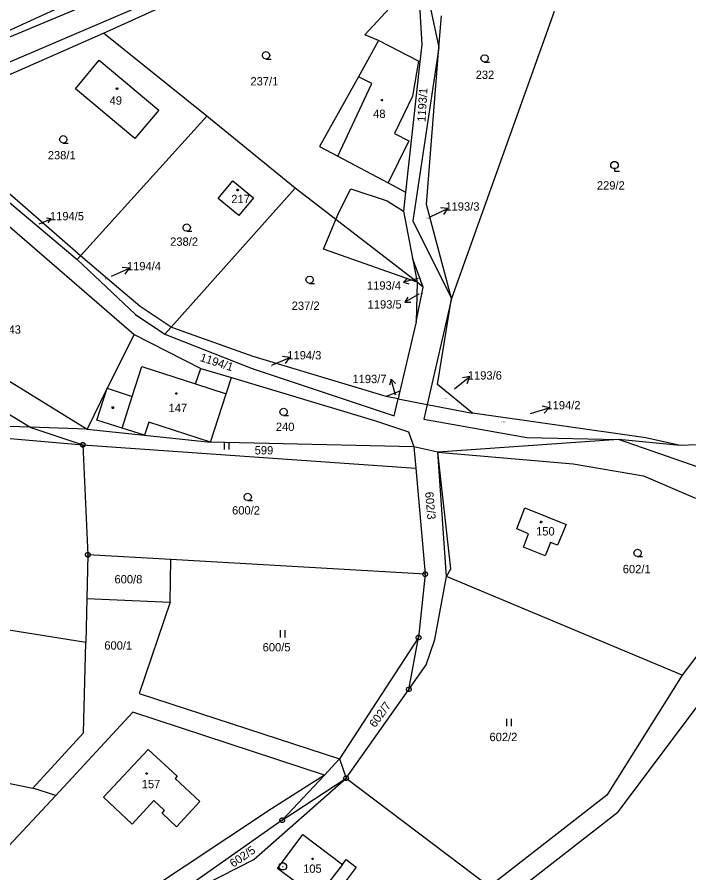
# Model space of a CAD drawing. Extents: x -694465 to -690527, y -983694 to -978978.
# Drawn here: x -692275 to -692137.7, y -981883.1 to -981708.4 of the extents above; entities that cross this region are included whole.
import ezdxf

# ---------------------------------------------------------------- set-up
doc = ezdxf.new("R2010")
doc.units = 0
for name, color, linetype in [('Vrstva 1', 7, 'Continuous'), ('Vrstva 16', 7, 'Continuous'), ('Vrstva 18', 7, 'Continuous'), ('Vrstva 19', 7, 'Continuous'), ('Vrstva 24', 7, 'Continuous'), ('Vrstva 25', 7, 'Continuous'), ('Vrstva 29', 7, 'Continuous')]:
    doc.layers.add(name, color=color, linetype=linetype)

msp = doc.modelspace()

# ---------------------------------------------------------------- linework, layer by layer
at = {"layer": 'Vrstva 1'}
msp.add_line((-692272.4, -981792.13), (-692261.55, -981795.71), dxfattribs=at)
for points in [[(-692257.29, -981711.65), (-692205.67, -981688.24)], [(-692231.78, -981693.79), (-692280.66, -981714.19)], [(-692192.79, -981696.05), (-692188.8, -981714.62)], [(-692278.89, -981718.56), (-692230.3, -981697.74)], [(-692250.23, -981699), (-692281.2, -981713.23)], [(-692203.9, -981712.02), (-692193.1, -981700.2)], [(-692193.1, -981700.2), (-692192.27, -981713.96)], [(-692188.8, -981714.62), (-692188.29, -981708.14)], [(-692165.23, -981707.27), (-692186.21, -981765.83)], [(-692296.96, -981729.07), (-692257.29, -981711.65)], [(-692236.23, -981728.62), (-692257.29, -981711.65)], [(-692201.12, -981713.15), (-692203.9, -981712.02)], [(-692201.12, -981713.15), (-692205.25, -981720.56)], [(-692192.99, -981717.35), (-692201.12, -981713.15)], [(-692192.27, -981713.96), (-692192.67, -981717.51)], [(-692188.8, -981714.62), (-692194.09, -981749.95)], [(-692191.32, -981746.65), (-692188.8, -981714.62)], [(-692258.2, -981717.18), (-692246.03, -981727.37), (-692250.9, -981733.19), (-692263.07, -981723), (-692258.2, -981717.18)], [(-692192.99, -981717.35), (-692194.2, -981724.54)], [(-692192.67, -981717.51), (-692192.99, -981717.35)], [(-692192.67, -981717.51), (-692195.6, -981744.14)], [(-692205.25, -981720.56), (-692213.2, -981734.83)], [(-692202.48, -981721.94), (-692205.25, -981720.56)], [(-692209.46, -981736.81), (-692202.48, -981721.94)], [(-692194.2, -981724.54), (-692197.87, -981732.16)], [(-692296.96, -981729.07), (-692262.73, -981757.9)], [(-692236.23, -981728.62), (-692262.05, -981757.15)], [(-692218.17, -981743.32), (-692236.23, -981728.62)], [(-692197.87, -981732.16), (-692194.95, -981733.63)], [(-692213.2, -981734.83), (-692209.46, -981736.81)], [(-692194.95, -981733.63), (-692199.19, -981742.24)], [(-692209.46, -981736.81), (-692199.19, -981742.24)], [(-692262.05, -981757.15), (-692280.84, -981740.82)], [(-692233.88, -981745.4), (-692230.87, -981741.79), (-692226.65, -981745.3), (-692229.65, -981748.88), (-692233.88, -981745.4)], [(-692243.51, -981771.7), (-692218.17, -981743.32)], [(-692209.86, -981749.73), (-692218.17, -981743.32)], [(-692209.12, -981748), (-692206.78, -981743.47)], [(-692206.78, -981743.47), (-692199.37, -981745.92)], [(-692199.19, -981742.24), (-692195.6, -981744.14)], [(-692195.6, -981744.14), (-692196.03, -981747.99)], [(-692199.37, -981745.92), (-692196.03, -981747.99)], [(-692186.21, -981765.83), (-692191.32, -981746.65)], [(-692209.86, -981749.73), (-692209.12, -981748)], [(-692196.03, -981747.99), (-692194.19, -981757.63)], [(-692279.142, -981748.931), (-692251.02, -981773.17)], [(-692212.4, -981755.73), (-692209.86, -981749.73)], [(-692193.26, -981762.53), (-692209.86, -981749.73)], [(-692194.09, -981749.95), (-692186.21, -981765.83)], [(-692193.26, -981762.53), (-692212.4, -981755.73)], [(-692262.73, -981757.9), (-692262.05, -981757.15)], [(-692254.63, -981763.4), (-692262.05, -981757.15)], [(-692194.19, -981757.63), (-692193.26, -981762.53)], [(-692192, -981763.5), (-692194.19, -981757.63)], [(-692262.73, -981757.9), (-692250.76, -981769.09)], [(-692193.26, -981762.53), (-692193.44, -981770.63)], [(-692192, -981763.5), (-692193.26, -981762.53)], [(-692249.84, -981767.44), (-692254.63, -981763.4)], [(-692193.44, -981770.63), (-692192, -981763.5)], [(-692186.21, -981765.83), (-692191.17, -981787.48)], [(-692189.06, -981783.4), (-692186.21, -981765.83)], [(-692243.51, -981771.7), (-692249.84, -981767.44)], [(-692250.76, -981769.09), (-692244.76, -981773.11)], [(-692193.44, -981770.63), (-692196.77, -981784.74)], [(-692251.02, -981773.17), (-692256.56, -981784.17)], [(-692251.02, -981773.17), (-692237.44, -981780.11)], [(-692244.76, -981773.11), (-692243.51, -981771.7)], [(-692244.76, -981773.11), (-692226.97, -981780.11)], [(-692240.7, -981772.7), (-692243.51, -981771.7)], [(-692226.77, -981777.67), (-692240.7, -981772.7)], [(-692199.6, -981785.85), (-692226.77, -981777.67)], [(-692251.44, -981785.82), (-692249.49, -981779.75)], [(-692249.49, -981779.75), (-692238.49, -981783.28)], [(-692238.49, -981783.28), (-692237.44, -981780.11)], [(-692237.44, -981780.11), (-692231.2, -981781.97)], [(-692226.97, -981780.11), (-692197.91, -981789.76)], [(-692232.27, -981785.28), (-692231.2, -981781.97)], [(-692231.2, -981781.97), (-692201.94, -981790.73)], [(-692276.89, -981782.51), (-692260.66, -981792.53)], [(-692238.49, -981783.28), (-692232.27, -981785.28)], [(-692181.96, -981789.26), (-692189.06, -981783.4)], [(-692256.56, -981784.17), (-692260.66, -981792.53)], [(-692258.65, -981790.66), (-692256.56, -981784.17)], [(-692256.56, -981784.17), (-692251.44, -981785.82)], [(-692235.44, -981795.15), (-692232.27, -981785.28)], [(-692196.77, -981784.74), (-692199.6, -981785.85)], [(-692196.77, -981784.74), (-692197.13, -981786.33)], [(-692272.4, -981792.13), (-692280.59, -981787.14)], [(-692253.52, -981792.3), (-692251.44, -981785.82)], [(-692197.13, -981786.33), (-692199.6, -981785.85)], [(-692197.91, -981789.76), (-692197.13, -981786.33)], [(-692197.13, -981786.33), (-692191.17, -981787.48)], [(-692191.17, -981787.48), (-692191.86, -981790.49)], [(-692191.17, -981787.48), (-692181.96, -981789.26)], [(-692253.52, -981792.3), (-692258.65, -981790.66)], [(-692201.94, -981790.73), (-692195, -981793.05)], [(-692191.86, -981790.49), (-692170.86, -981794.21)], [(-692146.51, -981794.26), (-692181.96, -981789.26)], [(-692272.4, -981792.13), (-692286.84, -981791.64)], [(-692260.66, -981792.53), (-692272.4, -981792.13)], [(-692260.66, -981792.53), (-692248.95, -981793.77)], [(-692248.95, -981793.77), (-692253.52, -981792.3)], [(-692248.09, -981791.08), (-692248.95, -981793.77)], [(-692235.44, -981795.15), (-692248.09, -981791.08)], [(-692287.43, -981793.47), (-692261.55, -981795.71)], [(-692248.95, -981793.77), (-692235.44, -981795.15)], [(-692195, -981793.05), (-692193.92, -981796.12)], [(-692170.86, -981794.21), (-692152.09, -981794.64)], [(-692139.51, -981795.86), (-692146.51, -981794.26)], [(-692261.55, -981795.71), (-692260.51, -981818.15)], [(-692261.55, -981795.71), (-692193.53, -981800.46)], [(-692193.92, -981796.12), (-692235.44, -981795.15)], [(-692152.09, -981794.64), (-692189.03, -981797.21)], [(-692139.51, -981795.86), (-692152.09, -981794.64)], [(-692119.15, -981806.07), (-692152.09, -981794.64)], [(-692136.04, -981795.7), (-692139.51, -981795.86)], [(-692193.92, -981796.12), (-692193.53, -981800.46)], [(-692189.03, -981797.21), (-692193.92, -981796.12)], [(-692186.33, -981821.04), (-692189.03, -981797.21)], [(-692189.03, -981797.21), (-692161.37, -981799.58)], [(-692187.24, -981822.58), (-692189.03, -981797.21)], [(-692161.37, -981799.58), (-692147.02, -981802.05)], [(-692193.53, -981800.46), (-692191.62, -981822.11)], [(-692147.02, -981802.05), (-692136.35, -981806.57)], [(-692162.81, -981812), (-692164.57, -981816.23), (-692166, -981815.65), (-692167.11, -981818.36), (-692171.53, -981816.58), (-692170.46, -981813.85), (-692172.9, -981812.87), (-692171.23, -981808.59), (-692162.81, -981812)], [(-692260.51, -981818.15), (-692260.72, -981827.06)], [(-692243.54, -981819.13), (-692260.51, -981818.15)], [(-692243.72, -981827.83), (-692243.54, -981819.13)], [(-692191.62, -981822.11), (-692243.54, -981819.13)], [(-692191.62, -981822.11), (-692192.95, -981835.08)], [(-692187.24, -981822.58), (-692186.33, -981821.04)], [(-692189.61, -981835.48), (-692187.24, -981822.58)], [(-692139.1, -981842.77), (-692187.24, -981822.58)], [(-692260.72, -981827.06), (-692260.94, -981836.06)], [(-692260.72, -981827.06), (-692243.72, -981827.83)], [(-692243.72, -981827.83), (-692250.03, -981846.51)], [(-692260.94, -981836.06), (-692300.55, -981829.71)], [(-692128.92, -981829.39), (-692139.1, -981842.77)], [(-692152.17, -981870.62), (-692124.32, -981833.57)], [(-692261.4, -981854.49), (-692260.94, -981836.06)], [(-692192.95, -981835.08), (-692209.09, -981859.82)], [(-692194.95, -981845.63), (-692192.95, -981835.08)], [(-692191.43, -981840.64), (-692189.61, -981835.48)], [(-692194.95, -981845.63), (-692191.43, -981840.64)], [(-692139.1, -981842.77), (-692154.49, -981867.24)], [(-692250.03, -981846.51), (-692209.09, -981859.82)], [(-692207.77, -981863.76), (-692194.95, -981845.63)], [(-692251.3, -981850.3), (-692267.06, -981867.3)], [(-692212.18, -981863.13), (-692251.3, -981850.3)], [(-692271.78, -981865.78), (-692261.4, -981854.49)], [(-692308.11, -981858.37), (-692271.78, -981865.78)], [(-692242.71, -981863.81), (-692237.61, -981868.56), (-692242.41, -981873.67), (-692245.36, -981870.94), (-692244.84, -981870.38), (-692247.02, -981868.36), (-692251.45, -981873.14), (-692257.32, -981867.66), (-692248.18, -981857.88), (-692242.3, -981863.36), (-692242.71, -981863.81)], [(-692209.09, -981859.82), (-692212.18, -981863.13)], [(-692209.09, -981859.82), (-692207.77, -981863.76)], [(-692226.61, -981880.38), (-692207.77, -981863.76)], [(-692212.18, -981863.13), (-692222.98, -981870.05)], [(-692212.18, -981863.13), (-692220.82, -981872.37)], [(-692220.82, -981872.37), (-692207.77, -981863.76)], [(-692207.77, -981863.76), (-692178.46, -981885.9)], [(-692267.06, -981867.3), (-692271.78, -981865.78)], [(-692267.06, -981867.3), (-692298.87, -981901.26)], [(-692154.49, -981867.24), (-692178.46, -981885.9)], [(-692222.98, -981870.05), (-692249.34, -981887.51)], [(-692194.4, -981903.52), (-692152.17, -981870.62)], [(-692220.82, -981872.37), (-692247.01, -981890.78)], [(-692212.93, -981887.14), (-692213.73, -981888.21), (-692221.78, -981882.18), (-692216.62, -981875.29), (-692208.46, -981881.4)], [(-692247.01, -981890.78), (-692226.61, -981880.38)], [(-692208.46, -981881.4), (-692212.93, -981887.14)], [(-692208.46, -981881.4), (-692207.71, -981880.4), (-692205.7, -981881.91)], [(-692205.7, -981881.91), (-692210.81, -981888.73), (-692212.93, -981887.14)]]:
    msp.add_lwpolyline(points, dxfattribs=at)
at = {"layer": 'Vrstva 24'}
for points in [[(-692261.396, -981795.234), (-692261.146, -981795.416), (-692261.05, -981795.71), (-692261.146, -981796.004), (-692261.396, -981796.186), (-692261.704, -981796.186), (-692261.954, -981796.004), (-692262.05, -981795.71), (-692261.954, -981795.416), (-692261.704, -981795.234)], [(-692260.356, -981817.674), (-692260.106, -981817.856), (-692260.01, -981818.15), (-692260.106, -981818.444), (-692260.356, -981818.626), (-692260.664, -981818.626), (-692260.914, -981818.444), (-692261.01, -981818.15), (-692260.914, -981817.856), (-692260.664, -981817.674)], [(-692191.466, -981821.634), (-692191.216, -981821.816), (-692191.12, -981822.11), (-692191.216, -981822.404), (-692191.466, -981822.586), (-692191.774, -981822.586), (-692192.024, -981822.404), (-692192.12, -981822.11), (-692192.024, -981821.816), (-692191.774, -981821.634)], [(-692192.796, -981834.604), (-692192.546, -981834.786), (-692192.45, -981835.08), (-692192.546, -981835.374), (-692192.796, -981835.556), (-692193.104, -981835.556), (-692193.354, -981835.374), (-692193.45, -981835.08), (-692193.354, -981834.786), (-692193.104, -981834.604)], [(-692194.796, -981845.154), (-692194.546, -981845.336), (-692194.45, -981845.63), (-692194.546, -981845.924), (-692194.796, -981846.106), (-692195.104, -981846.106), (-692195.354, -981845.924), (-692195.45, -981845.63), (-692195.354, -981845.336), (-692195.104, -981845.154)], [(-692207.616, -981863.284), (-692207.366, -981863.466), (-692207.27, -981863.76), (-692207.366, -981864.054), (-692207.616, -981864.236), (-692207.924, -981864.236), (-692208.174, -981864.054), (-692208.27, -981863.76), (-692208.174, -981863.466), (-692207.924, -981863.284)], [(-692220.666, -981871.894), (-692220.416, -981872.076), (-692220.32, -981872.37), (-692220.416, -981872.664), (-692220.666, -981872.846), (-692220.974, -981872.846), (-692221.224, -981872.664), (-692221.32, -981872.37), (-692221.224, -981872.076), (-692220.974, -981871.894)], [(-692220.486, -981881.066), (-692220.15, -981881.26), (-692219.956, -981881.596), (-692219.956, -981881.984), (-692220.15, -981882.32), (-692220.486, -981882.514), (-692220.874, -981882.514), (-692221.21, -981882.32), (-692221.404, -981881.984), (-692221.404, -981881.596), (-692221.21, -981881.26), (-692220.874, -981881.066)]]:
    msp.add_lwpolyline(points, close=True, dxfattribs=at)
for points in [[(-692261.669, -981795.71), (-692261.43, -981795.71)], [(-692260.629, -981818.15), (-692260.39, -981818.15)], [(-692191.739, -981822.11), (-692191.5, -981822.11)], [(-692193.069, -981835.08), (-692192.83, -981835.08)], [(-692195.069, -981845.63), (-692194.83, -981845.63)], [(-692207.889, -981863.76), (-692207.65, -981863.76)], [(-692220.939, -981872.37), (-692220.7, -981872.37)], [(-692220.73, -981881.79), (-692220.63, -981881.79)]]:
    msp.add_lwpolyline(points, dxfattribs=at)
at = {"layer": 'Vrstva 25'}
for points in [[(-692224.09, -981716.94), (-692224.465, -981716.839), (-692224.739, -981716.565), (-692224.84, -981716.19), (-692224.739, -981715.815), (-692224.465, -981715.541), (-692224.09, -981715.44), (-692223.715, -981715.541), (-692223.441, -981715.815), (-692223.34, -981716.19), (-692223.441, -981716.565), (-692223.715, -981716.839), (-692224.09, -981716.94), (-692223.09, -981716.941)], [(-692179.46, -981717.58), (-692179.835, -981717.479), (-692180.109, -981717.205), (-692180.21, -981716.83), (-692180.109, -981716.455), (-692179.835, -981716.181), (-692179.46, -981716.08), (-692179.085, -981716.181), (-692178.811, -981716.455), (-692178.71, -981716.83), (-692178.811, -981717.205), (-692179.085, -981717.479), (-692179.46, -981717.58), (-692178.46, -981717.581)], [(-692265.55, -981734.09), (-692265.925, -981733.989), (-692266.199, -981733.715), (-692266.3, -981733.34), (-692266.199, -981732.965), (-692265.925, -981732.691), (-692265.55, -981732.59), (-692265.175, -981732.691), (-692264.901, -981732.965), (-692264.8, -981733.34), (-692264.901, -981733.715), (-692265.175, -981733.989), (-692265.55, -981734.09), (-692264.55, -981734.091)], [(-692152.929, -981739.324), (-692153.124, -981739.324), (-692153.459, -981739.13), (-692153.654, -981738.794), (-692153.654, -981738.407), (-692153.461, -981738.07), (-692153.124, -981737.876), (-692152.737, -981737.876), (-692152.4, -981738.07), (-692152.206, -981738.405), (-692152.206, -981738.795), (-692152.399, -981739.13), (-692152.737, -981739.324), (-692152.929, -981739.324), (-692152.93, -981739.85), (-692151.929, -981739.848)], [(-692240.3, -981752.11), (-692240.675, -981752.009), (-692240.949, -981751.735), (-692241.05, -981751.36), (-692240.949, -981750.985), (-692240.675, -981750.711), (-692240.3, -981750.61), (-692239.925, -981750.711), (-692239.651, -981750.985), (-692239.55, -981751.36), (-692239.651, -981751.735), (-692239.925, -981752.009), (-692240.3, -981752.11), (-692239.3, -981752.111)], [(-692215.23, -981762.76), (-692215.605, -981762.659), (-692215.879, -981762.385), (-692215.98, -981762.01), (-692215.879, -981761.635), (-692215.605, -981761.361), (-692215.23, -981761.26), (-692214.855, -981761.361), (-692214.581, -981761.635), (-692214.48, -981762.01), (-692214.581, -981762.385), (-692214.855, -981762.659), (-692215.23, -981762.76), (-692214.23, -981762.761)], [(-692220.52, -981789.73), (-692220.895, -981789.629), (-692221.169, -981789.355), (-692221.27, -981788.98), (-692221.169, -981788.605), (-692220.895, -981788.331), (-692220.52, -981788.23), (-692220.145, -981788.331), (-692219.871, -981788.605), (-692219.77, -981788.98), (-692219.871, -981789.355), (-692220.145, -981789.629), (-692220.52, -981789.73), (-692219.52, -981789.731)], [(-692232.67, -981795.14), (-692232.67, -981796.64)], [(-692231.67, -981796.64), (-692231.67, -981795.14)], [(-692227.85, -981807.09), (-692228.225, -981806.989), (-692228.499, -981806.715), (-692228.6, -981806.34), (-692228.499, -981805.965), (-692228.225, -981805.691), (-692227.85, -981805.59), (-692227.475, -981805.691), (-692227.201, -981805.965), (-692227.1, -981806.34), (-692227.201, -981806.715), (-692227.475, -981806.989), (-692227.85, -981807.09), (-692226.85, -981807.091)], [(-692148.22, -981818.54), (-692148.595, -981818.439), (-692148.869, -981818.165), (-692148.97, -981817.79), (-692148.869, -981817.415), (-692148.595, -981817.141), (-692148.22, -981817.04), (-692147.845, -981817.141), (-692147.571, -981817.415), (-692147.47, -981817.79), (-692147.571, -981818.165), (-692147.845, -981818.439), (-692148.22, -981818.54), (-692147.22, -981818.541)], [(-692221.23, -981833.53), (-692221.23, -981835.03)], [(-692220.23, -981835.03), (-692220.23, -981833.53)], [(-692174.99, -981851.68), (-692174.99, -981853.18)], [(-692173.99, -981853.18), (-692173.99, -981851.68)]]:
    msp.add_lwpolyline(points, dxfattribs=at)
for points in [[(-692254.463, -981722.828), (-692254.375, -981722.98), (-692254.463, -981723.132), (-692254.637, -981723.132), (-692254.725, -981722.98), (-692254.637, -981722.828)], [(-692200.363, -981725.178), (-692200.275, -981725.33), (-692200.363, -981725.482), (-692200.537, -981725.482), (-692200.625, -981725.33), (-692200.537, -981725.178)], [(-692229.833, -981743.518), (-692229.745, -981743.67), (-692229.833, -981743.822), (-692230.007, -981743.822), (-692230.095, -981743.67), (-692230.007, -981743.518)], [(-692242.373, -981785.088), (-692242.285, -981785.24), (-692242.373, -981785.392), (-692242.547, -981785.392), (-692242.635, -981785.24), (-692242.547, -981785.088)], [(-692255.323, -981787.978), (-692255.235, -981788.13), (-692255.323, -981788.282), (-692255.497, -981788.282), (-692255.585, -981788.13), (-692255.497, -981787.978)], [(-692167.833, -981811.308), (-692167.745, -981811.46), (-692167.833, -981811.612), (-692168.007, -981811.612), (-692168.095, -981811.46), (-692168.007, -981811.308)], [(-692248.393, -981862.648), (-692248.305, -981862.8), (-692248.393, -981862.952), (-692248.567, -981862.952), (-692248.655, -981862.8), (-692248.567, -981862.648)], [(-692214.523, -981880.098), (-692214.435, -981880.25), (-692214.523, -981880.402), (-692214.697, -981880.402), (-692214.785, -981880.25), (-692214.697, -981880.098)]]:
    msp.add_lwpolyline(points, close=True, dxfattribs=at)
at = {"layer": 'Vrstva 29'}
for points in [[(-692190.59, -981749.14), (-692186.949, -981747.485), (-692188.442, -981747.34)], [(-692187.822, -981748.706), (-692186.949, -981747.485)], [(-692270.47, -981750.62), (-692267.992, -981749.6), (-692268.989, -981749.467)], [(-692268.606, -981750.396), (-692267.992, -981749.6)], [(-692255.67, -981761.28), (-692252.012, -981759.661), (-692253.504, -981759.502)], [(-692252.897, -981760.873), (-692252.012, -981759.661)], [(-692195.194, -981761.704), (-692196.043, -981762.51)], [(-692193.01, -981761.78), (-692196.043, -981762.51), (-692194.921, -981762.842)], [(-692192.93, -981764.93), (-692195.75, -981766.606), (-692194.519, -981766.59)], [(-692195.147, -981765.532), (-692195.75, -981766.606)], [(-692222.91, -981779.47), (-692219.246, -981777.866), (-692220.737, -981777.7)], [(-692220.136, -981779.074), (-692219.246, -981777.866)], [(-692185.59, -981784.3), (-692182.507, -981781.752), (-692183.986, -981782.002)], [(-692183.031, -981783.158), (-692182.507, -981781.752)], [(-692197.67, -981785.54), (-692198.563, -981782.301), (-692198.88, -981783.521)], [(-692197.665, -981783.186), (-692198.563, -981782.301)], [(-692170.08, -981789.33), (-692166.249, -981788.18), (-692167.71, -981787.835)], [(-692167.278, -981789.272), (-692166.249, -981788.18)]]:
    msp.add_lwpolyline(points, dxfattribs=at)

# ---------------------------------------------------------------- texts
at = {"layer": 'Vrstva 16'}
for s, p in [('1193/3', (-692187.467, -981747.9)), ('1194/5', (-692268.257, -981749.87)), ('1194/4', (-692252.537, -981760.07)), ('1193/4', (-692203.492, -981764.03)), ('1193/5', (-692203.358, -981767.89)), ('1194/3', (-692219.767, -981778.27)), ('1193/7', (-692206.451, -981783.11)), ('1193/6', (-692182.887, -981782.39)), ('1194/2', (-692166.817, -981788.47))]:
    msp.add_text(s, height=1.7, dxfattribs=at).set_placement(p)
at = {"layer": 'Vrstva 18'}
for s, height, p in [('237/1', 1.7, (-692227.296, -981722.34)), ('232', 1.7, (-692181.283, -981721.01)), ('238/1', 1.7, (-692268.693, -981737.43)), ('229/2', 1.7, (-692156.514, -981743.59)), ('1194/5', 0.2, (-692270.424, -981750.62)), ('1193/3', 0.2, (-692191.404, -981749.53)), ('238/2', 1.7, (-692243.694, -981755.07)), ('1194/4', 0.2, (-692257.064, -981761.92)), ('1193/4', 0.2, (-692192.964, -981761.78)), ('237/2', 1.7, (-692218.857, -981768.16)), ('1193/5', 0.2, (-692192.884, -981764.93)), ('243', 1.7, (-692277.985, -981773.02)), ('1194/3', 0.2, (-692223.654, -981779.82)), ('1193/7', 0.2, (-692197.624, -981785.54)), ('1193/6', 0.2, (-692188.054, -981786.37)), ('240', 1.7, (-692222.105, -981792.88)), ('1194/2', 0.2, (-692176.024, -981791.13)), ('599', 1.7, (-692226.431, -981797.67)), ('600/2', 1.7, (-692231.05, -981809.94)), ('602/1', 1.7, (-692151.226, -981821.92)), ('600/8', 1.7, (-692255.073, -981824)), ('600/1', 1.7, (-692257.149, -981837.52)), ('600/5', 1.7, (-692224.804, -981837.88)), ('602/2', 1.7, (-692178.457, -981856.21))]:
    msp.add_text(s, height=height, dxfattribs=at).set_placement(p)
for s, rotation, p in [('1193/1', 86.40204, (-692191.545, -981729.818)), ('1194/1', 341.99851, (-692237.737, -981778.561)), ('602/3', 274.90515, (-692191.62, -981805.363)), ('602/7', 53.97263, (-692201.82, -981853.571)), ('602/5', 34.20558, (-692230.811, -981882.073))]:
    msp.add_text(s, height=1.7, rotation=rotation, dxfattribs=at).set_placement(p)
at = {"layer": 'Vrstva 19'}
for s, p in [('49', (-692256.065, -981726.26)), ('48', (-692202.235, -981728.97)), ('217', (-692231.203, -981746.37)), ('147', (-692244.026, -981789.04)), ('150', (-692168.947, -981814.22)), ('157', (-692249.507, -981865.82)), ('105', (-692216.54, -981883.08))]:
    msp.add_text(s, height=1.7, dxfattribs=at).set_placement(p)

doc.saveas('drawing.dxf')
